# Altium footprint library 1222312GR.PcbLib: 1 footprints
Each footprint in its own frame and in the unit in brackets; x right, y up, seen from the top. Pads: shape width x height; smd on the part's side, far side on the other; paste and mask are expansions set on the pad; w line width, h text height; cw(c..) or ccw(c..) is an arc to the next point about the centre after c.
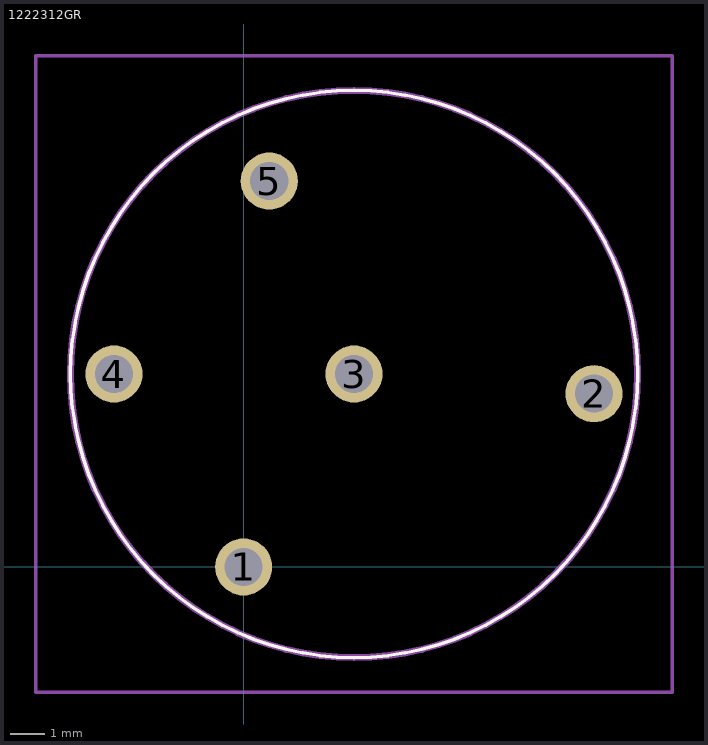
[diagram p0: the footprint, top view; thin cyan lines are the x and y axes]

## 1222312GR [mm]
pads (5):
  round 1.65 hole 1.1: 1(0,0) 2(10.13,5.01) 3(3.19,5.58) 4(-3.75,5.58) 5(0.74,11.16)
Top Overlay:
  lines w0.1: -5.01,5.58 -5.01,5.58 ; -5.01,5.58 ccw(c3.19,5.58) 11.39,5.58 ; -5.01,5.58 cw(c3.19,5.58) 11.39,5.58 ; 11.39,5.58 11.39,5.58
Mechanical 15:
  lines w0.2: -5.01,5.58 -5.01,5.58 ; -5.01,5.58 ccw(c3.19,5.58) 11.39,5.58 ; -5.01,5.58 cw(c3.19,5.58) 11.39,5.58 ; 11.39,5.58 11.39,5.58
Mechanical 20:
  lines w0.1: -6.01,-3.62 12.39,-3.62 12.39,14.78 -6.01,14.78 -6.01,-3.62
3D body "122-2312-GR.stp": height 5.8, standoff -4.65, extent -10,-3.376 10,3.376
